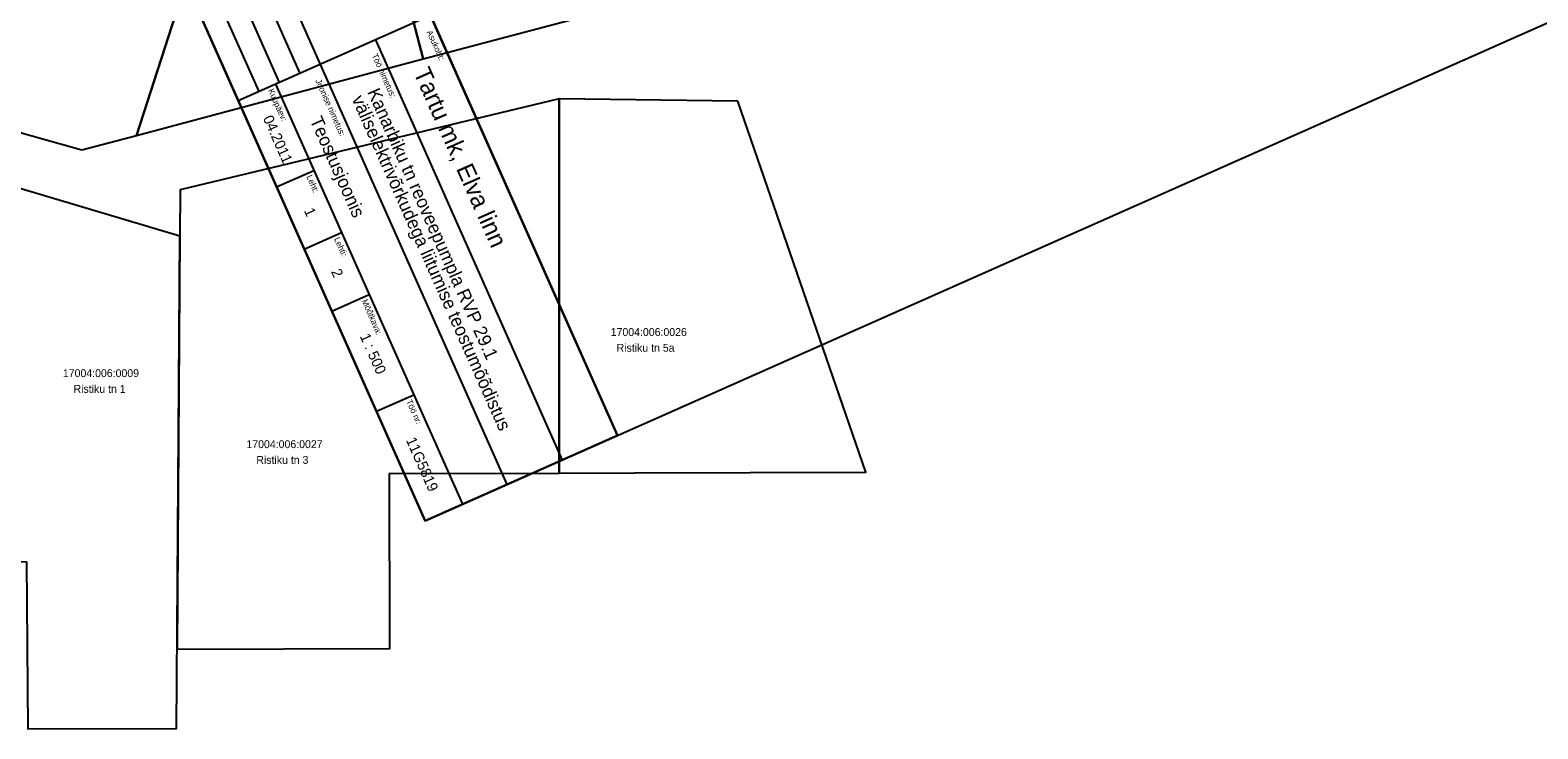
# Model space of a CAD drawing. Extents: x 642747 to 644424, y 6457048 to 6458238.
# Drawn here: x 643970.7 to 644143, y 6457449.2 to 6457529.1 of the extents above; entities that cross this region are included whole.
import ezdxf

# ---------------------------------------------------------------- set-up
doc = ezdxf.new("R2010")
doc.units = 0
doc.layers.add('PIIR', color=7, linetype='Continuous')
doc.layers.add('VORMISTUS', color=7, linetype='Continuous')

msp = doc.modelspace()

# ---------------------------------------------------------------- linework, layer by layer
at = {"layer": 'PIIR'}
for points in [[(643976.63, 6457515.36), (643982.89, 6457517.02), (644002.28, 6457577.05), (643979.35, 6457603.09), (643976.97, 6457593.64), (643971.26, 6457567.81), (643957.55, 6457524.74), (643955.72, 6457521.24)], [(643982.89, 6457517.02), (644015.62, 6457525.76), (644002.28, 6457577.05)], [(644002.28, 6457577.05), (644015.62, 6457525.76), (644038.14, 6457531.7), (644040.39, 6457536.24)], [(643987.84, 6457505.49), (643987.52, 6457458.28), (644011.82, 6457458.35), (644011.79, 6457478.35), (644031.18, 6457478.41), (644031.16, 6457516.2), (644031.16, 6457521.18), (643987.87, 6457510.79)], [(644051.6, 6457520.91), (644031.16, 6457521.18), (644031.16, 6457516.2), (644031.18, 6457478.41), (644039.79, 6457478.44), (644066.21, 6457478.51)], [(643987.84, 6457505.49), (643963.66, 6457512.68), (643960.91, 6457468.35), (643970.33, 6457468.27), (643970.46, 6457449.16), (643987.46, 6457449.2)]]:
    msp.add_lwpolyline(points, close=True, dxfattribs=at)
at = {"layer": 'VORMISTUS'}
for p, q in [((643870.38, 6457800.45), (644015.85, 6457472.95)), ((644037.82, 6457482.7), (644001.69, 6457564.04)), ((643986.74, 6457557.4), (644001.53, 6457524.11)), ((643989.08, 6457558.44), (644025.21, 6457477.1)), ((643982.06, 6457555.32), (643996.85, 6457522.03)), ((643984.4, 6457556.36), (643999.19, 6457523.07)), ((643979.72, 6457554.28), (644015.85, 6457472.95)), ((644015.85, 6457472.95), (644180.43, 6457546.05)), ((643994.51, 6457520.99), (644016.48, 6457530.75)), ((644010.17, 6457527.95), (644031.51, 6457479.9)), ((643998.78, 6457522.89), (644020.12, 6457474.84)), ((643998.89, 6457511.13), (644003.16, 6457513.02)), ((644002.04, 6457504.02), (644006.31, 6457505.92)), ((644005.2, 6457496.92), (644009.47, 6457498.81)), ((644010.29, 6457485.47), (644014.55, 6457487.36)), ((644037.82, 6457482.7), (644015.85, 6457472.95)), ((644015.85, 6457472.95), (644037.82, 6457482.7))]:
    msp.add_line(p, q, dxfattribs=at)
msp.add_lwpolyline([(644001.69, 6457564.04), (644037.82, 6457482.7), (644015.85, 6457472.95), (643979.72, 6457554.28)], close=True, dxfattribs=at)

# ---------------------------------------------------------------- texts
at = {"layer": 'PIIR'}
for s, p in [('17004:006:0026', (644037.06, 6457494.08)), ('Ristiku tn 5a', (644037.73, 6457492.28)), ('17004:006:0009', (643974.47, 6457489.38)), ('Ristiku tn 1', (643975.69, 6457487.58)), ('17004:006:0027', (643995.44, 6457481.26)), ('Ristiku tn 3', (643996.57, 6457479.46))]:
    msp.add_text(s, height=0.9, dxfattribs=at).set_placement(p)
at = {"layer": 'VORMISTUS'}
for s, height, p in [('Asukoht:', 0.7, (644016.01, 6457528.85)), ('Töö nimetus:', 0.7, (644009.74, 6457526.18)), ('Tartu mk, Elva linn', 2, (644014.48, 6457524.23)), ('Joonise nimetus:', 0.7, (644003.3, 6457523.27)), ('Kuupäev:', 0.7, (643997.89, 6457522.16)), ('väliselektrivõrkudega liitumise teostumõõdistus', 1.5, (644007.44, 6457521.2)), ('Kanarbiku tn reoveepumpla RVP 29.1 ', 1.5, (644009.22, 6457521.99)), ('04.2011', 1.2, (643997.3, 6457518.98)), ('Teostusjoonis', 1.5, (644002.65, 6457518.77)), ('Leht:', 0.7, (644002.27, 6457512.3)), ('1', 1.2, (644001.99, 6457508.42)), ('Lehti:', 0.7, (644005.43, 6457505.19)), ('2', 1.2, (644005.09, 6457501.45)), ('Mõõtkava:', 0.7, (644008.58, 6457498.09)), ('1 : 500', 1.2, (644008.37, 6457494.06)), ('Töö nr:', 0.7, (644013.67, 6457486.63)), ('11G5819', 1.2, (644013.64, 6457482.19))]:
    msp.add_text(s, height=height, rotation=293.9493, dxfattribs=at).set_placement(p)

doc.saveas('drawing.dxf')
